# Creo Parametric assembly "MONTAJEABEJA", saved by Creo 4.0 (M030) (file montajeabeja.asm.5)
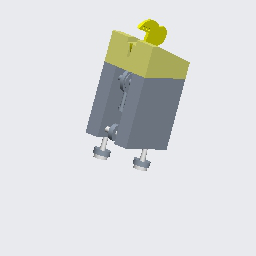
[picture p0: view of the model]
Units: millimeter Newton Second (mmNs); MM, TONNE, SECS

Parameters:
  MODELED_BY = "aj"

Created from: MMNS_ASM_DESIGN.ASM

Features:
  1. datum plane "ASM_RIGHT"
  2. datum plane "ASM_TOP"
  3. datum plane "ASM_FRONT"
  4. coordinate system
  5. component "LADOSUNIONESABEJA"
  6. component "EJECENTROABEJA"
  7. component "EJECENTROABEJA"
  8. component "EJECENTROABEJA"
  9. component "LADOSUNIONESABEJA"
  10. component "EJELATERALABEJA"
  11. component "EJELATERALABEJA"
  12. component "EJERUEDASCENTROABEJA"
  13. component "RODAMIENTOABEJA"
  14. component "SOPORTEPESO"
  15. component "EJERUEDASCENTROABEJA"
  16. component "RODAMIENTOABEJA"
  17. component "SOPORTEPESO"
  18. component "ELEVADORABEJA"
  19. component "ABEJAENSI"

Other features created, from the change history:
  component "LADOSUNIONESABEJA.PRT"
